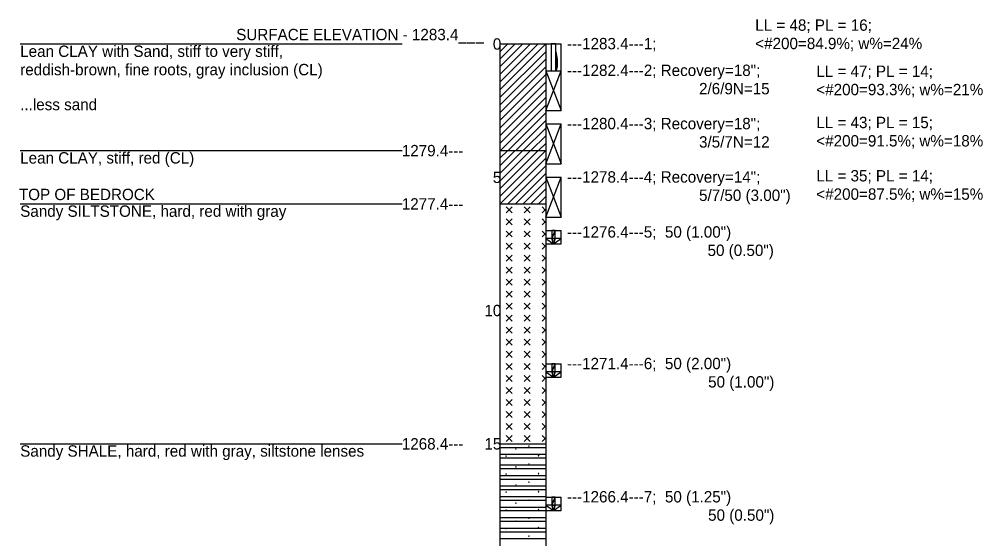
# Model space of a CAD drawing. Extents: x 7 to 126, y 24 to 56.
# Drawn here: x 55.3 to 65.81, y 44.45 to 50.11 of the extents above; entities that cross this region are included whole.
import ezdxf

# ---------------------------------------------------------------- set-up
doc = ezdxf.new("R2010")
doc.units = 0

# ---------------------------------------------------------------- blocks, each defined once
blk = doc.blocks.new('POINT_DISPLAY')
blk.add_line((0, 0), (0, 0))

msp = doc.modelspace()

# ---------------------------------------------------------------- linework, layer by layer
for points in [[(55.31, 49.842), (59.477, 49.842)], [(60.543, 49.758), (60.627, 49.842)], [(60.543, 49.675), (60.71, 49.842)], [(60.543, 49.592), (60.793, 49.842)], [(60.543, 49.508), (60.877, 49.842)], [(60.543, 49.425), (60.96, 49.842)], [(60.543, 49.342), (61.043, 49.842)], [(60.543, 49.842), (60.543, 39.086)], [(60.543, 49.842), (61.043, 49.842)], [(61.043, 49.842), (61.21, 49.842)], [(61.043, 49.842), (61.043, 39.086)], [(61.21, 49.551), (61.21, 49.842)], [(60.543, 49.258), (61.043, 49.758)], [(60.543, 49.175), (61.043, 49.675)], [(60.543, 49.092), (61.043, 49.592)], [(60.543, 49.008), (61.043, 49.508)], [(61.043, 49.551), (61.21, 49.551)], [(61.043, 49.551), (61.21, 49.115)], [(61.043, 49.115), (61.21, 49.551)], [(61.043, 49.551), (61.21, 49.551)], [(61.21, 49.115), (61.21, 49.551)], [(60.543, 48.925), (61.043, 49.425)], [(60.543, 48.842), (61.043, 49.342)], [(60.543, 48.758), (61.043, 49.258)], [(60.547, 48.679), (61.043, 49.175)], [(60.631, 48.679), (61.043, 49.092)], [(61.043, 49.115), (61.21, 49.115)], [(60.714, 48.679), (61.043, 49.008)], [(61.043, 48.97), (61.21, 48.534)], [(61.043, 48.534), (61.21, 48.97)], [(61.043, 48.97), (61.21, 48.97)], [(61.21, 48.534), (61.21, 48.97)], [(60.797, 48.679), (61.043, 48.925)], [(60.881, 48.679), (61.043, 48.842)], [(60.964, 48.679), (61.043, 48.758)], [(55.31, 48.679), (59.477, 48.679)], [(60.543, 48.679), (61.043, 48.679)], [(60.543, 48.596), (60.627, 48.679)], [(60.543, 48.512), (60.71, 48.679)], [(60.543, 48.429), (60.793, 48.679)], [(60.543, 48.346), (60.877, 48.679)], [(60.543, 48.262), (60.96, 48.679)], [(60.543, 48.179), (61.043, 48.679)], [(60.545, 48.098), (61.043, 48.596)], [(60.629, 48.098), (61.043, 48.512)], [(61.043, 48.534), (61.21, 48.534)], [(60.712, 48.098), (61.043, 48.429)], [(60.795, 48.098), (61.043, 48.346)], [(61.043, 48.388), (61.21, 47.952)], [(61.043, 47.952), (61.21, 48.388)], [(61.043, 48.388), (61.21, 48.388)], [(61.21, 47.952), (61.21, 48.388)], [(60.879, 48.098), (61.043, 48.262)], [(60.962, 48.098), (61.043, 48.179)], [(55.31, 48.098), (59.477, 48.098)], [(60.543, 48.098), (61.043, 48.098)], [(60.675, 48.065), (60.609, 47.999)], [(60.609, 48.065), (60.675, 47.999)], [(60.872, 48.065), (60.806, 47.999)], [(60.806, 48.065), (60.872, 47.999)], [(61.003, 48.065), (61.043, 48.024)], [(61.043, 48.04), (61.003, 47.999)], [(60.675, 47.934), (60.609, 47.868)], [(60.609, 47.934), (60.675, 47.868)], [(60.872, 47.934), (60.806, 47.868)], [(60.806, 47.934), (60.872, 47.868)], [(61.003, 47.934), (61.043, 47.893)], [(61.043, 47.952), (61.21, 47.952)], [(61.043, 47.909), (61.003, 47.868)], [(60.675, 47.802), (60.609, 47.737)], [(60.609, 47.802), (60.675, 47.737)], [(60.872, 47.802), (60.806, 47.737)], [(60.806, 47.802), (60.872, 47.737)], [(61.003, 47.802), (61.043, 47.762)], [(61.043, 47.777), (61.003, 47.737)], [(61.043, 47.807), (61.21, 47.807)], [(61.21, 47.662), (61.21, 47.807)], [(60.675, 47.671), (60.609, 47.605)], [(60.609, 47.671), (60.675, 47.605)], [(60.872, 47.671), (60.806, 47.605)], [(60.806, 47.671), (60.872, 47.605)], [(61.003, 47.671), (61.043, 47.63)], [(61.043, 47.646), (61.003, 47.605)], [(61.043, 47.662), (61.21, 47.662)], [(60.675, 47.54), (60.609, 47.474)], [(60.609, 47.54), (60.675, 47.474)], [(60.872, 47.54), (60.806, 47.474)], [(60.806, 47.54), (60.872, 47.474)], [(61.003, 47.54), (61.043, 47.499)], [(61.043, 47.515), (61.003, 47.474)], [(60.675, 47.409), (60.609, 47.343)], [(60.609, 47.409), (60.675, 47.343)], [(60.872, 47.409), (60.806, 47.343)], [(60.806, 47.409), (60.872, 47.343)], [(61.003, 47.409), (61.043, 47.368)], [(61.043, 47.384), (61.003, 47.343)], [(60.675, 47.277), (60.609, 47.212)], [(60.609, 47.277), (60.675, 47.212)], [(60.872, 47.277), (60.806, 47.212)], [(60.806, 47.277), (60.872, 47.212)], [(61.003, 47.277), (61.043, 47.237)], [(61.043, 47.252), (61.003, 47.212)], [(60.675, 47.146), (60.609, 47.081)], [(60.609, 47.146), (60.675, 47.081)], [(60.872, 47.146), (60.806, 47.081)], [(60.806, 47.146), (60.872, 47.081)], [(61.003, 47.146), (61.043, 47.105)], [(61.043, 47.121), (61.003, 47.081)], [(60.675, 47.015), (60.609, 46.949)], [(60.609, 47.015), (60.675, 46.949)], [(60.872, 47.015), (60.806, 46.949)], [(60.806, 47.015), (60.872, 46.949)], [(61.003, 47.015), (61.043, 46.974)], [(61.043, 46.99), (61.003, 46.949)], [(60.675, 46.884), (60.609, 46.818)], [(60.609, 46.884), (60.675, 46.818)], [(60.872, 46.884), (60.806, 46.818)], [(60.806, 46.884), (60.872, 46.818)], [(61.003, 46.884), (61.043, 46.843)], [(61.043, 46.859), (61.003, 46.818)], [(60.675, 46.752), (60.609, 46.687)], [(60.609, 46.752), (60.675, 46.687)], [(60.872, 46.752), (60.806, 46.687)], [(60.806, 46.752), (60.872, 46.687)], [(61.003, 46.752), (61.043, 46.712)], [(61.043, 46.728), (61.003, 46.687)], [(60.675, 46.621), (60.609, 46.556)], [(60.609, 46.621), (60.675, 46.556)], [(60.872, 46.621), (60.806, 46.556)], [(60.806, 46.621), (60.872, 46.556)], [(61.003, 46.621), (61.043, 46.581)], [(61.043, 46.596), (61.003, 46.556)], [(60.675, 46.49), (60.609, 46.424)], [(60.609, 46.49), (60.675, 46.424)], [(60.872, 46.49), (60.806, 46.424)], [(60.806, 46.49), (60.872, 46.424)], [(61.003, 46.49), (61.043, 46.449)], [(61.043, 46.465), (61.003, 46.424)], [(60.675, 46.359), (60.609, 46.293)], [(60.609, 46.359), (60.675, 46.293)], [(60.872, 46.359), (60.806, 46.293)], [(60.806, 46.359), (60.872, 46.293)], [(61.003, 46.359), (61.043, 46.318)], [(61.043, 46.353), (61.21, 46.353)], [(61.21, 46.208), (61.21, 46.353)], [(61.043, 46.334), (61.003, 46.293)], [(60.675, 46.228), (60.609, 46.162)], [(60.609, 46.228), (60.675, 46.162)], [(60.872, 46.228), (60.806, 46.162)], [(60.806, 46.228), (60.872, 46.162)], [(61.003, 46.228), (61.043, 46.187)], [(61.043, 46.203), (61.003, 46.162)], [(61.043, 46.208), (61.21, 46.208)], [(60.675, 46.096), (60.609, 46.031)], [(60.609, 46.096), (60.675, 46.031)], [(60.872, 46.096), (60.806, 46.031)], [(60.806, 46.096), (60.872, 46.031)], [(61.003, 46.096), (61.043, 46.056)], [(61.043, 46.071), (61.003, 46.031)], [(60.675, 45.965), (60.609, 45.899)], [(60.609, 45.965), (60.675, 45.899)], [(60.872, 45.965), (60.806, 45.899)], [(60.806, 45.965), (60.872, 45.899)], [(61.003, 45.965), (61.043, 45.924)], [(61.043, 45.94), (61.003, 45.899)], [(60.675, 45.834), (60.609, 45.768)], [(60.609, 45.834), (60.675, 45.768)], [(60.872, 45.834), (60.806, 45.768)], [(60.806, 45.834), (60.872, 45.768)], [(61.003, 45.834), (61.043, 45.793)], [(61.043, 45.809), (61.003, 45.768)], [(60.675, 45.703), (60.609, 45.637)], [(60.609, 45.703), (60.675, 45.637)], [(60.872, 45.703), (60.806, 45.637)], [(60.806, 45.703), (60.872, 45.637)], [(61.003, 45.703), (61.043, 45.662)], [(61.043, 45.678), (61.012, 45.646), (61.003, 45.637)], [(60.675, 45.571), (60.609, 45.506)], [(60.609, 45.571), (60.675, 45.506)], [(60.872, 45.571), (60.806, 45.506)], [(60.806, 45.571), (60.872, 45.506)], [(61.003, 45.571), (61.032, 45.542), (61.043, 45.531)], [(61.043, 45.546), (61.033, 45.536), (61.003, 45.506)], [(55.31, 45.481), (59.477, 45.481)], [(60.543, 45.481), (61.043, 45.481)], [(60.543, 45.481), (61.043, 45.481)], [(60.543, 45.442), (61.043, 45.442)], [(60.719, 45.425), (60.717, 45.428), (60.714, 45.428), (60.712, 45.426), (60.714, 45.423), (60.717, 45.423), (60.719, 45.425)], [(60.861, 45.457), (60.859, 45.46), (60.856, 45.46), (60.855, 45.457), (60.856, 45.455), (60.859, 45.455), (60.861, 45.457)], [(60.543, 45.367), (61.043, 45.367)], [(60.543, 45.327), (61.043, 45.327)], [(60.614, 45.347), (60.612, 45.349), (60.609, 45.349), (60.607, 45.347), (60.609, 45.344), (60.612, 45.344), (60.614, 45.347)], [(60.967, 45.353), (60.965, 45.356), (60.962, 45.356), (60.96, 45.353), (60.962, 45.35), (60.965, 45.35), (60.967, 45.353)], [(60.543, 45.252), (61.043, 45.252)], [(60.543, 45.212), (61.043, 45.212)], [(60.719, 45.229), (60.717, 45.232), (60.714, 45.232), (60.712, 45.229), (60.714, 45.226), (60.717, 45.226), (60.719, 45.229)], [(60.861, 45.261), (60.859, 45.263), (60.856, 45.263), (60.855, 45.261), (60.856, 45.258), (60.859, 45.258), (60.861, 45.261)], [(60.543, 45.137), (61.043, 45.137)], [(60.543, 45.097), (61.043, 45.097)], [(60.614, 45.15), (60.612, 45.153), (60.609, 45.153), (60.607, 45.15), (60.609, 45.147), (60.612, 45.147), (60.614, 45.15)], [(60.967, 45.156), (60.965, 45.159), (60.962, 45.159), (60.96, 45.156), (60.962, 45.153), (60.965, 45.153), (60.967, 45.156)], [(60.543, 45.022), (61.043, 45.022)], [(60.543, 44.983), (61.043, 44.983)], [(60.719, 45.032), (60.717, 45.035), (60.714, 45.035), (60.712, 45.032), (60.714, 45.029), (60.717, 45.029), (60.719, 45.032)], [(60.861, 45.064), (60.859, 45.067), (60.856, 45.067), (60.855, 45.064), (60.856, 45.061), (60.859, 45.061), (60.861, 45.064)], [(60.543, 44.907), (61.043, 44.907)], [(60.614, 44.953), (60.612, 44.956), (60.609, 44.956), (60.607, 44.953), (60.609, 44.95), (60.612, 44.95), (60.614, 44.953)], [(60.967, 44.959), (60.965, 44.962), (60.962, 44.962), (60.96, 44.959), (60.962, 44.957), (60.965, 44.957), (60.967, 44.959)], [(61.043, 44.9), (61.21, 44.9)], [(61.21, 44.755), (61.21, 44.9)], [(60.543, 44.868), (61.043, 44.868)], [(60.543, 44.792), (61.043, 44.792)], [(60.719, 44.835), (60.717, 44.838), (60.714, 44.838), (60.712, 44.835), (60.714, 44.832), (60.717, 44.832), (60.719, 44.835)], [(60.861, 44.867), (60.859, 44.87), (60.856, 44.87), (60.855, 44.867), (60.856, 44.864), (60.859, 44.864), (60.861, 44.867)], [(60.967, 44.762), (60.965, 44.765), (60.962, 44.765), (60.96, 44.762), (60.962, 44.76), (60.965, 44.76), (60.967, 44.762)], [(60.543, 44.753), (61.043, 44.753)], [(60.543, 44.678), (61.043, 44.678)], [(60.614, 44.756), (60.612, 44.759), (60.609, 44.759), (60.607, 44.756), (60.609, 44.753), (60.612, 44.753), (60.614, 44.756)], [(60.861, 44.67), (60.859, 44.673), (60.856, 44.673), (60.855, 44.67), (60.856, 44.667), (60.859, 44.667), (60.861, 44.67)], [(61.043, 44.755), (61.21, 44.755)], [(60.543, 44.638), (61.043, 44.638)], [(60.543, 44.563), (61.043, 44.563)], [(60.614, 44.559), (60.612, 44.562), (60.609, 44.562), (60.607, 44.559), (60.609, 44.556), (60.612, 44.556), (60.614, 44.559)], [(60.719, 44.638), (60.717, 44.641), (60.714, 44.641), (60.712, 44.638), (60.714, 44.635), (60.717, 44.635), (60.719, 44.638)], [(60.967, 44.566), (60.965, 44.569), (60.962, 44.569), (60.96, 44.566), (60.962, 44.563), (60.965, 44.563), (60.967, 44.566)], [(60.543, 44.523), (61.043, 44.523)], [(60.861, 44.473), (60.859, 44.476), (60.856, 44.476), (60.855, 44.473), (60.856, 44.47), (60.859, 44.47), (60.861, 44.473)], [(60.543, 44.448), (61.043, 44.448)]]:
    msp.add_lwpolyline(points)
for points in [[(61.102, 49.842), (61.102, 49.551), (61.152, 49.551), (61.152, 49.842)], [(61.166, 49.675), (61.16, 49.717), (61.152, 49.757), (61.166, 49.675)], [(61.152, 49.757), (61.152, 49.551), (61.166, 49.675), (61.152, 49.757)], [(61.152, 49.551), (61.166, 49.592), (61.166, 49.675), (61.152, 49.551)], [(61.166, 49.592), (61.168, 49.633), (61.166, 49.675), (61.166, 49.592)], [(61.152, 49.551), (61.161, 49.551), (61.166, 49.592), (61.152, 49.551)], [(61.11, 47.72), (61.043, 47.72), (61.127, 47.662), (61.11, 47.72)], [(61.11, 47.72), (61.143, 47.72), (61.143, 47.807), (61.11, 47.72)], [(61.11, 47.72), (61.143, 47.807), (61.11, 47.807), (61.11, 47.72)], [(61.11, 47.72), (61.127, 47.662), (61.143, 47.72), (61.11, 47.72)], [(61.127, 47.662), (61.21, 47.72), (61.143, 47.72), (61.127, 47.662)], [(61.11, 46.266), (61.143, 46.266), (61.143, 46.353), (61.11, 46.266)], [(61.11, 46.266), (61.143, 46.353), (61.11, 46.353), (61.11, 46.266)], [(61.11, 46.266), (61.043, 46.266), (61.127, 46.208), (61.11, 46.266)], [(61.11, 46.266), (61.127, 46.208), (61.143, 46.266), (61.11, 46.266)], [(61.127, 46.208), (61.21, 46.266), (61.143, 46.266), (61.127, 46.208)], [(61.11, 44.813), (61.143, 44.813), (61.143, 44.9), (61.11, 44.813)], [(61.11, 44.813), (61.143, 44.9), (61.11, 44.9), (61.11, 44.813)], [(61.11, 44.813), (61.043, 44.813), (61.127, 44.755), (61.11, 44.813)], [(61.11, 44.813), (61.127, 44.755), (61.143, 44.813), (61.11, 44.813)], [(61.127, 44.755), (61.21, 44.813), (61.143, 44.813), (61.127, 44.755)]]:
    msp.add_lwpolyline(points, close=True)

# ---------------------------------------------------------------- block references
at = {"xscale": 0.01, "yscale": 0.01}
for p in [(60.583, 49.825), (60.749, 49.825), (60.549, 49.758), (60.616, 49.725), (60.649, 49.792), (60.772, 49.761), (60.816, 49.725), (60.849, 49.792), (60.916, 49.725), (60.969, 49.808), (61.016, 49.758), (60.583, 49.658), (60.683, 49.692), (60.749, 49.625), (60.833, 49.649), (60.983, 49.658), (60.549, 49.525), (60.616, 49.592), (60.683, 49.558), (60.768, 49.548), (60.849, 49.592), (60.967, 49.574), (61.016, 49.525), (60.616, 49.392), (60.649, 49.492), (60.716, 49.458), (60.783, 49.425), (60.819, 49.478), (60.862, 49.392), (60.883, 49.492), (60.949, 49.458), (60.983, 49.392), (60.549, 49.325), (60.649, 49.292), (60.749, 49.358), (60.816, 49.292), (60.916, 49.325), (60.583, 49.258), (60.783, 49.225), (60.883, 49.192), (60.983, 49.258), (60.549, 49.092), (60.583, 49.158), (60.649, 49.125), (60.749, 49.158), (60.772, 49.095), (60.849, 49.125), (60.969, 49.142), (61.016, 49.092), (60.583, 48.992), (60.616, 49.058), (60.683, 49.025), (60.816, 49.058), (60.833, 48.983), (60.916, 49.058), (60.983, 48.992), (60.616, 48.925), (60.683, 48.892), (60.749, 48.958), (60.768, 48.881), (60.849, 48.925), (60.967, 48.907), (60.549, 48.858), (60.649, 48.825), (60.716, 48.792), (60.783, 48.758), (60.819, 48.811), (60.883, 48.825), (60.949, 48.792), (61.016, 48.858), (60.616, 48.725), (60.749, 48.692), (60.862, 48.725), (60.983, 48.725)]:
    msp.add_blockref('POINT_DISPLAY', p, dxfattribs=at)

# ---------------------------------------------------------------- texts
for s, p in [('LL = 48; PL = 16;', (63.327, 49.986)), ('SURFACE ELEVATION - 1283.4___', (57.666, 49.883)), ('Lean CLAY with Sand, stiff to very stiff,', (55.31, 49.701)), ('0', (60.465, 49.78)), ('---1283.4---1;', (61.273, 49.784)), ('<#200=84.9%; w%=24%', (63.327, 49.786)), ('reddish-brown, fine roots, gray inclusion (CL)', (55.31, 49.501)), ('---1282.4---2; Recovery=18";', (61.273, 49.493)), ('LL = 47; PL = 14;', (63.993, 49.483)), ('2/6/9N=15', (62.714, 49.293)), ('<#200=93.3%; w%=21%', (63.993, 49.283)), ('...less sand', (55.31, 49.12)), ('---1280.4---3; Recovery=18";', (61.273, 48.912)), ('LL = 43; PL = 15;', (63.993, 48.924)), ('3/5/7N=12', (62.714, 48.712)), ('<#200=91.5%; w%=18%', (63.993, 48.724)), ('Lean CLAY, stiff, red (CL)', (55.31, 48.538)), ('1279.4---', (59.472, 48.617)), ('5', (60.465, 48.326)), ('---1278.4---4; Recovery=14";', (61.273, 48.33)), ('LL = 35; PL = 14;', (63.993, 48.343)), ('TOP OF BEDROCK', (55.296, 48.139)), ('5/7/50 (3.00")', (62.714, 48.13)), ('<#200=87.5%; w%=15%', (63.993, 48.143)), ('1277.4---', (59.472, 48.036)), ('Sandy SILTSTONE, hard, red with gray', (55.31, 47.957)), ('---1276.4---5;  50 (1.00")', (61.273, 47.73)), ('50 (0.50")', (62.807, 47.53)), ('10', (60.373, 46.873)), ('---1271.4---6;  50 (2.00")', (61.273, 46.295)), ('50 (1.00")', (62.813, 46.095)), ('1268.4---', (59.472, 45.419)), ('15', (60.373, 45.419)), ('Sandy SHALE, hard, red with gray, siltstone lenses', (55.31, 45.341)), ('---1266.4---7;  50 (1.25")', (61.273, 44.842)), ('50 (0.50")', (62.813, 44.642))]:
    msp.add_text(s, height=0.124).set_placement(p)

doc.saveas('drawing.dxf')
